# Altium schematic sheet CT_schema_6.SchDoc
size 226 x 144 mm
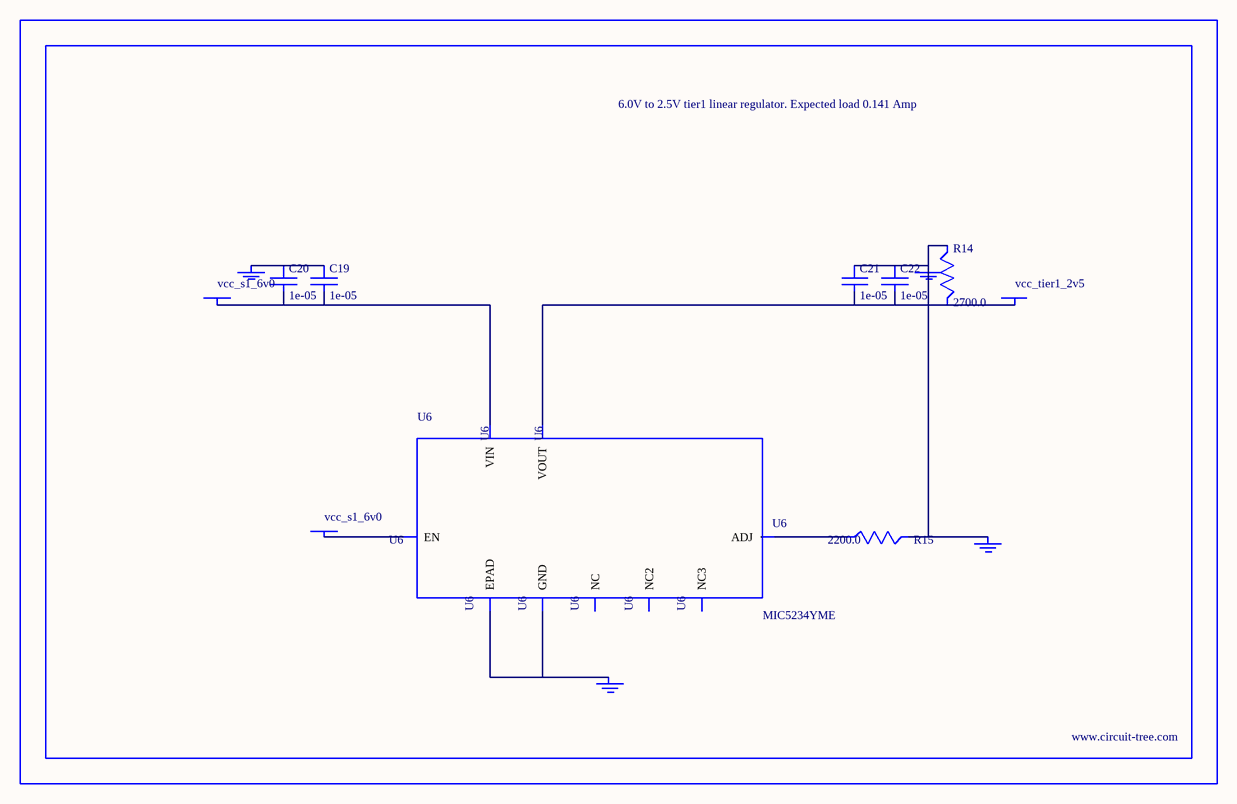
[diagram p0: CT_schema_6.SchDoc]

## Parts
BORDER5  (no value)
C19  1e-05  [C1210]
C20  1e-05  [C1210]
C21  1e-05  [C1210]
C22  1e-05  [C1210]
GND_INSTANCE_5_0  (no value)
GND_INSTANCE_5_1  (no value)
GND_INSTANCE_5_2  (no value)
GND_INSTANCE_5_3  (no value)
POWER_INSTANCE_5_0  vcc_tier1_2v5
POWER_INSTANCE_5_1  vcc_s1_6v0
POWER_INSTANCE_5_2  vcc_s1_6v0
R14  2700.0  [R0603]
R15  2200.0  [R0603]
U6  MIC5234YME  [SOIC-8_EP]

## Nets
NetC19_1: C19.1 C20.1 GND_INSTANCE_5_3.0(GND)
NetC19_2: C19.2 C20.2 POWER_INSTANCE_5_2.0(PWR) U6.8(VIN)
NetC21_1: C21.1 C22.1 GND_INSTANCE_5_0.0(GND) GND_INSTANCE_5_1.0(GND) R14.1 R15.2
NetC21_2: C21.2 C22.2 POWER_INSTANCE_5_0.0(PWR) R14.2 U6.1(VOUT)
NetGND_INSTANCE_5_2_0: GND_INSTANCE_5_2.0(GND) U6.7(GND) U6.EPAD
NetPOWER_INSTANCE_5_1_0: POWER_INSTANCE_5_1.0(PWR) U6.5(EN)
NetR15_1: R15.1 U6.4(ADJ)

Not connected (* = marked no-connect by the designer): U6 2(NC) 3(NC2) 6(NC3)

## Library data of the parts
BORDER5 = BORDER_PAGE5
C19-C22 = C1210C106K5PACTU
GND_INSTANCE_5_0-GND_INSTANCE_5_3 = GND
POWER_INSTANCE_5_0-POWER_INSTANCE_5_2 = PWR
R14 = RC0603JR-072K7L
R15 = RC0603JR-072K2L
